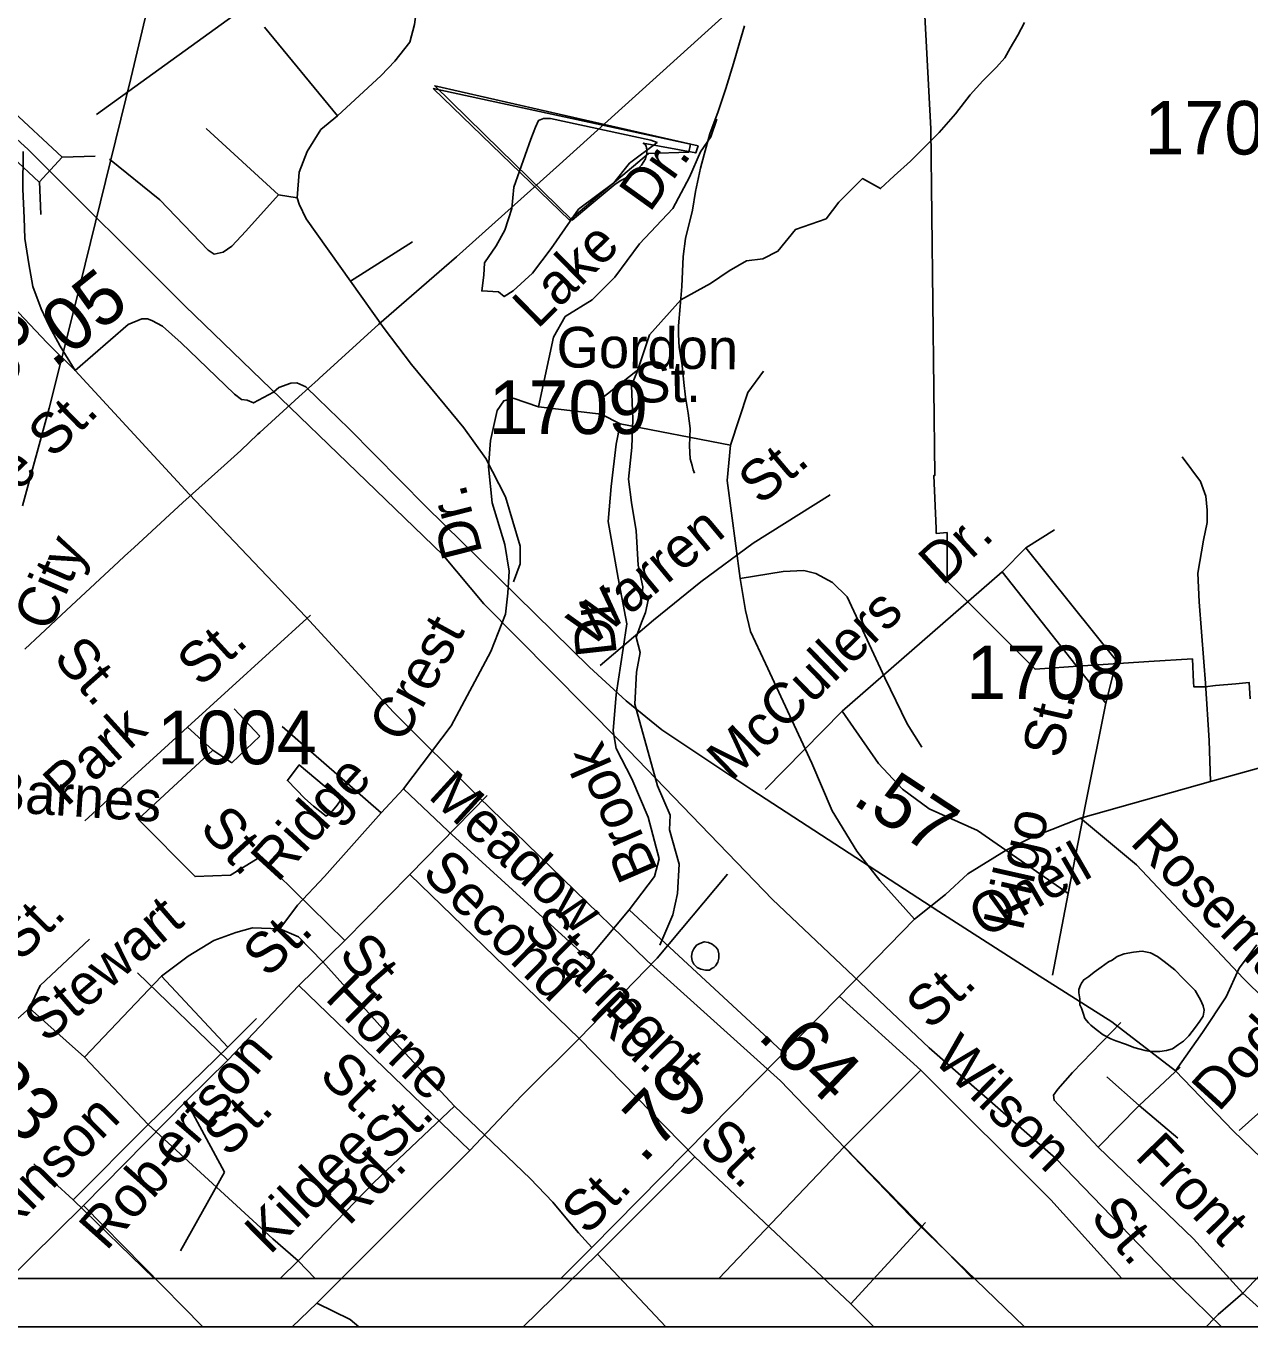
# Model space of a CAD drawing. Extents: x 2169602 to 2449496, y 721995 to 810662.
# Drawn here: x 2400191 to 2403047, y 758895 to 761931 of the extents above; entities that cross this region are included whole.
import ezdxf

# ---------------------------------------------------------------- set-up
doc = ezdxf.new("R2010")
doc.units = 0
doc.layers.add('Default', color=7, linetype='Continuous')

msp = doc.modelspace()

# ---------------------------------------------------------------- linework, layer by layer
at = {"layer": 'Default'}
for p, q in [((2400355.4, 761724.6), (2402242.2, 763086.8)), ((2400918.3, 761721.5), (2400747.8, 761928.8)), ((2400780.1, 761537.2), (2400611.9, 761691.6)), ((2400275.4, 761624.8), (2400352.5, 761627.7)), ((2400222.9, 761568.2), (2400225.9, 761491.1)), ((2400823.8, 761530.3), (2400780.1, 761537.2)), ((2400948.2, 761335.7), (2401093.3, 761427.8)), ((2401834.9, 760953), (2401577.1, 761002.9)), ((2402523.8, 760713.7), (2402590.6, 760755.2)), ((2402468.5, 760657.3), (2402523.8, 760713.7)), ((2402735.7, 760450), (2402523.8, 760713.7)), ((2402095.4, 760332.5), (2402468.5, 760657.3)), ((2402710.4, 760350.9), (2402468.5, 760657.3)), ((2400855.2, 760556.4), (2400568, 760294.8)), ((2402710.4, 760350.9), (2402735.7, 760450)), ((2400737.1, 760274), (2400676.5, 760337.8)), ((2401915.7, 760149.4), (2402095.4, 760332.5)), ((2400568, 760294.8), (2400328.7, 760076.2)), ((2400671.7, 760211.8), (2400737.1, 760274)), ((2401019.5, 760094.8), (2400788.6, 760296.6)), ((2400627, 760241.3), (2400671.7, 760211.8)), ((2401086.5, 759951), (2401266.8, 760135.2)), ((2400934.9, 759797), (2400737.1, 759991.6)), ((2400934.9, 759797), (2401086.5, 759951)), ((2401086.5, 759951), (2401482.2, 759568.1)), ((2401664, 759755.5), (2401828.3, 759951.8)), ((2402586, 759716.3), (2402622.9, 759906.4)), ((2401598.7, 759868.5), (2401502.7, 759754.4)), ((2401965.4, 759528.6), (2401598.7, 759868.5)), ((2400828, 759691.7), (2400934.9, 759797)), ((2401482.2, 759568.1), (2401664, 759755.5)), ((2400507.7, 759714), (2400328, 759525.1)), ((2400662.1, 759517.8), (2400451.5, 759721.2)), ((2400662.1, 759517.8), (2400828, 759691.7)), ((2400828, 759691.7), (2401226.9, 759307.2)), ((2402279.3, 759494.4), (2402088.6, 759667.3)), ((2400005.5, 759466.4), (2400199, 759639.1)), ((2400199, 759639.1), (2400328, 759525.1)), ((2400662, 759548.1), (2400728.8, 759614.9)), ((2401482.2, 759568.1), (2401751.6, 759291.9)), ((2400328, 759525.1), (2400476.4, 759367.8)), ((2400564.8, 759422.1), (2400662.1, 759517.8)), ((2403021.4, 759353.5), (2403214.9, 759526.3)), ((2402279.3, 759494.4), (2402099.9, 759315.6)), ((2402788.4, 759412.3), (2402884.2, 759501.3)), ((2402788.4, 759412.3), (2402713.1, 759479.1)), ((2400325.5, 759178.8), (2400564.8, 759422.1)), ((2400564.8, 759422.1), (2400654.2, 759256.2)), ((2402692.6, 759314.8), (2402788.4, 759412.3)), ((2402788.4, 759412.3), (2402879, 759335.4)), ((2400476.4, 759367.8), (2400301.1, 759191.6)), ((2402099.9, 759315.6), (2402400.6, 759007.9)), ((2400301.1, 759191.6), (2400209.6, 759275.4)), ((2401524.4, 759064.7), (2401751.6, 759291.9)), ((2401751.6, 759291.9), (2402115.8, 758949.2)), ((2400654.2, 759256.2), (2400552, 759072.7)), ((2400490.6, 759007.9), (2400301.1, 759191.6)), ((2400325.5, 759178.8), (2400604, 758895)), ((2402115.8, 758949.2), (2402290.1, 759139.1)), ((2401351.4, 758895), (2401524.4, 759064.7)), ((2400784.4, 759007.9), (2400826.2, 759049.7)), ((2400826.2, 759049.7), (2400865.5, 759007.9)), ((2394416.8, 759007.9), (2405610.9, 759007.9)), ((2394416.8, 759007.9), (2405610.9, 759007.9)), ((2403117.2, 758895), (2403030.2, 758974.2)), ((2400812, 758895), (2400869.5, 758950.7)), ((2397432.6, 758895), (2408626.7, 758895)), ((2397432.6, 758895), (2408626.7, 758895))]:
    msp.add_line(p, q, dxfattribs=at)
for points in [[(2400851, 766726.3), (2400842.5, 766575.8), (2400839.9, 766339.8), (2400835.6, 765996), (2400818.1, 765338.4), (2400840.8, 764831.1), (2400846.7, 763934.8), (2400833.1, 763794.7), (2400836.5, 763647.5), (2400818.5, 763466.1), (2400781.8, 763328.7), (2400733.9, 763084.7), (2400632.1, 762628), (2400510.6, 762123.4), (2400435.4, 761808.7), (2400306.2, 761280.1), (2400245.5, 761039), (2400183.1, 760811.5)], [(2396129.6, 763877.6), (2396680.6, 763791.4), (2397139, 763715.8), (2397435.1, 763663.6), (2397561.3, 763644.4), (2397693.5, 763605.1), (2397827.5, 763567.8), (2397896.5, 763550), (2397996.9, 763511.8), (2398101.8, 763473.6), (2398170.6, 763445.2), (2398269.9, 763394.4), (2398470.8, 763267.7), (2398593.3, 763184.4), (2398657.6, 763126.8), (2398901, 762898.2), (2399194.5, 762599.9), (2399845.9, 761961.9), (2400196.3, 761642.8)], [(2403048.5, 762768.7), (2402893.2, 762923.4), (2402644, 762698.7), (2402380.5, 762464.9), (2402119, 762227.3), (2401887.5, 762017.2), (2401435.7, 761608.3), (2401195.5, 761392.1), (2401166.7, 761367.8), (2401014.7, 761235.7), (2400875.2, 761108.9), (2400872.5, 761106.4), (2400827.7, 761065.7), (2400736.5, 760982.7), (2400732.2, 760978.7), (2400692.5, 760940.5), (2400653.2, 760905.2), (2400594.2, 760852.5), (2400557.2, 760818.9), (2400443.2, 760714.1), (2400421.2, 760693.8), (2400406.7, 760680.4), (2400297.5, 760578.8), (2400261.7, 760545.6)], [(2403048.5, 762768.7), (2402893.2, 762923.4), (2402644, 762698.7), (2402380.5, 762464.9), (2402119, 762227.3), (2401887.5, 762017.2), (2401435.7, 761608.3), (2401195.5, 761392.1), (2401166.7, 761367.8), (2401014.7, 761235.7), (2400875.2, 761108.9), (2400872.5, 761106.4), (2400827.7, 761065.7), (2400736.5, 760982.7), (2400732.2, 760978.7), (2400692.5, 760940.5), (2400653.2, 760905.2), (2400594.2, 760852.5), (2400557.2, 760818.9), (2400443.2, 760714.1), (2400421.2, 760693.8), (2400406.7, 760680.4), (2400297.5, 760578.8), (2400261.7, 760545.6)], [(2403047.4, 760360.8), (2403045.4, 760398.8), (2403013.9, 760396.1), (2402966.2, 760391.7), (2402942.4, 760389), (2402915.9, 760389.2), (2402914.9, 760399.7), (2402912.7, 760454), (2402810.7, 760448.4), (2402657.2, 760438.3), (2402545.4, 760430.1), (2402340.7, 760635.7), (2402340.4, 760748.9), (2402314.9, 760747.2), (2402314.7, 760758.7), (2402309.4, 760882.2), (2402311.4, 760881.8), (2402302.4, 761691.1), (2402269.7, 762307.4)], [(2403047.4, 760360.8), (2403045.4, 760398.8), (2403013.9, 760396.1), (2402966.2, 760391.7), (2402942.4, 760389), (2402915.9, 760389.2), (2402914.9, 760399.7), (2402912.7, 760454), (2402810.7, 760448.4), (2402657.2, 760438.3), (2402545.4, 760430.1), (2402340.7, 760635.7), (2402340.4, 760748.9), (2402314.9, 760747.2), (2402314.7, 760758.7), (2402309.4, 760882.2), (2402311.4, 760881.8), (2402302.4, 761691.1), (2402269.7, 762307.4)], [(2400918.3, 761721.5), (2401019.6, 761816), (2401051.9, 761849.4), (2401086.4, 761893.1), (2401098, 761934.6), (2401104.9, 761987.6), (2401111.8, 762095.8), (2401107.2, 762170.7)], [(2401670.2, 759786.2), (2401700.2, 759856.9), (2401711, 759906.8), (2401715.1, 759975), (2401692.7, 760055.6), (2401694.3, 760089.7), (2401664.4, 760157.9), (2401612, 760348.4), (2401615.3, 760423.2), (2401624.5, 760469), (2401615.1, 760504.7), (2401627.2, 760538.9), (2401636.6, 760562.7), (2401643.2, 760590.9), (2401628.2, 760596.7), (2401630.5, 760622.7), (2401619.5, 760672.7), (2401614.5, 760753.4), (2401603.7, 760819.1), (2401597, 760874), (2401604.5, 760947.2), (2401607, 761013.7), (2401604.2, 761092.1), (2401618, 761126.2), (2401646.1, 761210.8), (2401719.3, 761292.3), (2401788.3, 761330.6), (2401831.6, 761359.7), (2401872.3, 761383), (2401910.6, 761387.9), (2401945.5, 761405.4), (2401986.3, 761456.1), (2402057.8, 761481.1), (2402087.7, 761520.2), (2402142.6, 761575.1), (2402185.1, 761551.8), (2402216.9, 761581.8), (2402255.1, 761615.8), (2402322.1, 761682.3), (2402360.1, 761726.5), (2402393.9, 761770.9), (2402423.4, 761802.9), (2402455.6, 761835), (2402475.3, 761857.1), (2402487.2, 761879.3), (2402505.4, 761909.4), (2402521, 761939.5)], [(2401751.2, 760887.3), (2401747.5, 760895.2), (2401745.2, 760905.2), (2401741.1, 760921.3), (2401738.9, 760951.2), (2401740.9, 760991.5), (2401736.2, 761027.5), (2401730.3, 761065.3), (2401726.2, 761099.2), (2401722.3, 761139.1), (2401715.5, 761181.1), (2401713.2, 761211), (2401713.2, 761231.3), (2401717.6, 761276.9), (2401721, 761323), (2401724.5, 761393.1), (2401730.3, 761435.2), (2401746.1, 761501.4), (2401753.2, 761545.3), (2401765.3, 761599.4), (2401773.1, 761631.5), (2401786.7, 761679.3), (2401806.3, 761731.5), (2401824.4, 761785.6), (2401842, 761843.7), (2401855.6, 761891.6), (2401867.4, 761931.6)], [(2401362.7, 761578.4), (2401465.4, 761478.4), (2401509.7, 761515.3), (2401565.7, 761561.8), (2401578.9, 761570.5), (2401601.4, 761581.9), (2401602.4, 761582.4), (2401626.9, 761606.4), (2401636.4, 761620.8), (2401639.7, 761633.9), (2401639.9, 761642.1), (2401637.9, 761651.1), (2401635.9, 761654.5), (2401631.4, 761657.4), (2401753.9, 761635), (2401759.2, 761651.5), (2401144.7, 761791.4), (2401296.7, 761642.6), (2401362.7, 761578.4)], [(2401362.7, 761578.4), (2401465.4, 761478.4), (2401509.7, 761515.3), (2401565.7, 761561.8), (2401578.9, 761570.5), (2401601.4, 761581.9), (2401602.4, 761582.4), (2401626.9, 761606.4), (2401636.4, 761620.8), (2401639.7, 761633.9), (2401639.9, 761642.1), (2401637.9, 761651.1), (2401635.9, 761654.5), (2401631.4, 761657.4), (2401753.9, 761635), (2401759.2, 761651.5), (2401144.7, 761791.4), (2401296.7, 761642.6), (2401362.7, 761578.4)], [(2400823.8, 761530.3), (2400828.4, 761590.2), (2400846.9, 761638.6), (2400879.1, 761689.3), (2400918.3, 761721.5)], [(2401386.6, 761042.8), (2401421.6, 761205), (2401449, 761253.2), (2401512.2, 761292.3), (2401565.4, 761344.7), (2401622.8, 761422.9), (2401700.2, 761505.2), (2401739.3, 761578.4), (2401765, 761637.4), (2401789.2, 761672.4), (2401803.3, 761714)], [(2400305.9, 761127.1), (2400240.3, 761191.4), (2400106.6, 761332.7), (2399930, 761516.8), (2399861.9, 761591.3), (2399786.3, 761687.1)], [(2400184.8, 761638.6), (2400183.6, 761550.3), (2400187.2, 761483.8), (2400188.2, 761435.2), (2400197.4, 761376.2), (2400207.5, 761323.2), (2400226.4, 761270.9), (2400245.4, 761231.2), (2400271.2, 761183.9), (2400305.9, 761127.1)], [(2400196.3, 761642.8), (2400562.8, 761277.1), (2401163.8, 760696.7), (2401259.1, 760582.5), (2401576.9, 760262.2), (2401932.9, 759892.4), (2402298.5, 759546.6), (2402594, 759288.4), (2402853.3, 759020), (2402980.7, 758895)], [(2400780.1, 761537.2), (2400704.1, 761452), (2400671.8, 761417.5), (2400651.1, 761403.6), (2400630.3, 761399), (2400616.5, 761408.3), (2400503.7, 761525.7), (2400386.2, 761620.2)], [(2400948.2, 761335.7), (2400844.6, 761480.8), (2400828.4, 761515.4), (2400823.8, 761530.3)], [(2401328.3, 760634.3), (2401344.4, 760675.7), (2401344.4, 760717.2), (2401309.9, 760832.4), (2401263.8, 760922.2), (2401213.1, 760993.6), (2401091, 761141), (2401026.5, 761225.1), (2400948.2, 761335.7)], [(2400768.8, 761076.7), (2400721.9, 761051.4), (2400707, 761057.8), (2400694, 761059.6), (2400677.6, 761071.6), (2400592.8, 761153.6), (2400553.1, 761192.1), (2400509.6, 761230.5), (2400485, 761243.8), (2400474.7, 761247.5), (2400461.7, 761247.6), (2400429.5, 761234.3), (2400305.9, 761127.1)], [(2400305.9, 761127.1), (2400572, 760838.3), (2400844.4, 760552), (2401048.8, 760330), (2401246.8, 760132), (2401640.3, 759749.8), (2401951.2, 759469.2), (2402272.2, 759135.6), (2402520.8, 758895)], [(2401625, 761133.1), (2401536.7, 761063.9)], [(2401834.9, 760953), (2401875.6, 761076.1), (2401912.2, 761126)], [(2402873.2, 759492.6), (2402724.3, 759607.3), (2402555.3, 759714.5), (2402320.7, 759864.6), (2401884.3, 760148.4), (2401675, 760288.4), (2401591.7, 760356.5), (2401506, 760434.7), (2401123.8, 760809.9), (2400944.1, 760992.2), (2400872.2, 761061.5), (2400843.8, 761089.3), (2400823, 761098.1), (2400809.1, 761097.5), (2400781.3, 761087.6), (2400768.8, 761076.7)], [(2401386.6, 761042.8), (2401328.2, 761062.9), (2401306, 761056.1), (2401290.6, 761033.8), (2401275.2, 760963.7), (2401270.1, 760902.1), (2401278.6, 760818.3), (2401308.6, 760720.8), (2401318.8, 760659.2), (2401315.4, 760607.9), (2401310.3, 760558.3), (2401276.1, 760471.1), (2401182.9, 760298.3), (2401071.7, 760151.2)], [(2401577.1, 761002.9), (2401533.5, 761025.3), (2401386.6, 761042.8)], [(2401598.7, 759868.5), (2401657.8, 759946.7), (2401668.6, 759987.5), (2401642.8, 760084.8), (2401604.5, 760174.6), (2401567.9, 760245.3), (2401561.3, 760286), (2401567.9, 760370.8), (2401584.6, 760478.1), (2401592.9, 760536.3), (2401572.9, 760642.8), (2401549.6, 760775), (2401556.3, 760856.5), (2401567.9, 760955.5), (2401577.1, 761002.9)], [(2401857.4, 760642), (2401827.4, 760870.7), (2401834.9, 760953)], [(2402954.9, 760168.3), (2402951.5, 760264.1), (2402942.9, 760397.5), (2402939.5, 760447.1), (2402928.4, 760587.4), (2402925, 760654.1), (2402938.7, 760731.1), (2402947.2, 760772.1), (2402947.2, 760801.2), (2402943.8, 760833.7), (2402931.8, 760867.9), (2402889.1, 760926.1)], [(2401531, 760438.5), (2401655.4, 760544.4), (2401766, 760634.3), (2401888.1, 760724.1), (2402067.7, 760837)], [(2401857.4, 760642), (2401958, 760657.8), (2402006.2, 760660.3), (2402033.7, 760653.6), (2402072.7, 760632.8), (2402106.8, 760598.7), (2402195, 760409.9), (2402247.4, 760302.6), (2402281.5, 760247.8)], [(2402264, 759846.9), (2402183.4, 759936.7), (2402129.3, 760005.7), (2402071.9, 760099.7), (2402024.5, 760211.2), (2401916.4, 760443.2), (2401881.5, 760518), (2401869.8, 760567.1), (2401857.4, 760642)], [(2400261.7, 760545.6), (2400247.2, 760532.1), (2400225, 760511.2), (2400188.7, 760477.2)], [(2400261.7, 760545.6), (2400247.2, 760532.1), (2400225, 760511.2), (2400188.7, 760477.2)], [(2402095.4, 760332.5), (2402180.6, 760210.4), (2402235.9, 760150.5), (2402298.1, 760104.5), (2402410.9, 760053.8), (2402622.9, 759906.4)], [(2402622.9, 759906.4), (2402664.3, 760118.3), (2402710.4, 760350.9)], [(2400737.1, 759991.6), (2400668.5, 759949.4), (2400585.5, 759946.2), (2400453.1, 760080.2), (2400627, 760241.3), (2400568, 760294.8)], [(2403170.4, 760228.2), (2402954.9, 760168.3), (2402651.3, 760082.4), (2402585, 760055.9), (2402540.3, 760038.7), (2402478.3, 760007.7), (2402388.9, 759952.7), (2402336.3, 759904.7), (2402264, 759846.9), (2402086.1, 759663.9), (2401947.2, 759522.6), (2401511.3, 759080.4), (2401438.7, 759007.9)], [(2400891.9, 760086.8), (2400905.8, 760098.9), (2400913.8, 760109), (2400917.5, 760112.9), (2400925.9, 760125), (2400828.9, 760206.6), (2400801.3, 760170.2), (2400841.4, 760128.4), (2400861.9, 760110.7), (2400891.9, 760086.8)], [(2401071.7, 760151.2), (2401019.5, 760094.8)], [(2401502.7, 759754.4), (2401176, 760052), (2401071.7, 760151.2)], [(2401019.5, 760094.8), (2400887.8, 759946), (2400824.5, 759879.2), (2400783.5, 759824.5)], [(2402651.3, 760082.4), (2402782.2, 759973.3), (2403031.9, 759708.2), (2403328.7, 759415.7), (2403366.3, 759381.5), (2403388.5, 759355.8), (2403393.7, 759338.7), (2403385.1, 759314.8), (2403339.8, 759261.8)], [(2400507.7, 759714), (2400569.9, 759760.1), (2400629.8, 759796.9), (2400680.5, 759815.3), (2400719.6, 759826.9), (2400783.5, 759824.5)], [(2400783.5, 759824.5), (2400827.1, 759805.7), (2400883.5, 759747.5), (2401044.3, 759567.9), (2401190.6, 759410.6)], [(2400199, 759639.1), (2400224.4, 759692.1), (2400339.6, 759800.4)], [(2401800, 759738.2), (2401805.5, 759746.2), (2401807.6, 759756.1), (2401807.6, 759766.2), (2401805.5, 759776.3), (2401799.6, 759782), (2401791.8, 759788.1), (2401783.4, 759792.1), (2401773.5, 759794), (2401763.5, 759789.9), (2401755.7, 759785.8), (2401749.5, 759777.8), (2401745.6, 759769.9), (2401743.6, 759759.6), (2401745.8, 759749.6), (2401749.5, 759741.7), (2401757.5, 759734), (2401765.9, 759729.9), (2401776.2, 759728), (2401786, 759728.1), (2401791.8, 759732.1), (2401795.9, 759733.9), (2401800, 759738.2)], [(2403062.9, 759786.9), (2403022, 759732.2), (2402991.7, 759665.3), (2402936.2, 759582.1), (2402873.2, 759492.6)], [(2402756.2, 759555.4), (2402766.3, 759551.5), (2402776.3, 759547.5), (2402790.5, 759543.7), (2402802.2, 759539.9), (2402814.7, 759537.7), (2402826.6, 759537.9), (2402836.4, 759538), (2402852.4, 759540.1), (2402866.1, 759544.1), (2402880.3, 759554.1), (2402892.2, 759562.4), (2402904.1, 759574.4), (2402919.6, 759594.4), (2402930.1, 759608.6), (2402937.9, 759620.4), (2402939.9, 759634.7), (2402937.7, 759644.4), (2402931.5, 759658.7), (2402919.4, 759680.4), (2402907.5, 759692.3), (2402891.3, 759708.2), (2402871.5, 759728.2), (2402847.1, 759748.1), (2402831.3, 759759.9), (2402815.1, 759768), (2402795.4, 759771.8), (2402775.1, 759769.6), (2402753.1, 759765.6), (2402737.1, 759759.5), (2402725.3, 759751.1), (2402716.8, 759747.1), (2402699.6, 759735.1), (2402683.4, 759723), (2402671.1, 759713), (2402659.2, 759705.2), (2402653.7, 759697.1), (2402651.6, 759692.9), (2402647.5, 759683), (2402647.3, 759674.9), (2402649.8, 759660.8), (2402650, 759646.9), (2402653.7, 759639), (2402657.8, 759627.1), (2402661.7, 759615.1), (2402670.3, 759604.9), (2402676, 759599.2), (2402687.9, 759589.2), (2402704.3, 759577), (2402722.2, 759567.5), (2402734.3, 759563.2), (2402756.2, 759555.4)], [(2400507.7, 759714), (2400662, 759548.1)], [(2402692.6, 759314.8), (2402590, 759424.3), (2402588.3, 759436.3), (2402598.5, 759450), (2402632.7, 759489.3), (2402745.6, 759605.6)], [(2400662, 759548.1), (2400547.6, 759436.7), (2400476.4, 759367.8)], [(2401226.9, 759307.2), (2401348.1, 759434.9), (2401482.2, 759568.1)], [(2402279.3, 759494.4), (2402582, 759191.6), (2402747.6, 759007.9)], [(2402873.2, 759492.6), (2403008.1, 759352.6), (2403206.8, 759160.8), (2403030.2, 758974.2), (2402972.5, 758923.9), (2402965.3, 758916.6)], [(2400826.2, 759049.7), (2401003, 759232.6), (2401190.6, 759410.6)], [(2401190.6, 759410.6), (2401367.6, 759241.2), (2401420.6, 759186.5), (2401454.8, 759145.4), (2401480.5, 759114.7), (2401511.3, 759080.4)], [(2400476.4, 759367.8), (2400767.2, 759101), (2400826.2, 759049.7)], [(2400869.5, 758950.7), (2401086.5, 759167.6), (2401226.9, 759307.2)], [(2401807.7, 759007.9), (2402099.9, 759315.6)], [(2403030.2, 758974.2), (2402915, 759101), (2402692.6, 759314.8)], [(2400045.2, 758895), (2400140.4, 758996.1), (2400325.5, 759178.8)], [(2401683.7, 758895), (2401524.4, 759064.7)], [(2400869.5, 758950.7), (2400947.7, 758912.4), (2400967.5, 758895)], [(2402115.8, 758949.2), (2402169.4, 758895)], [(2402965.3, 758916.6), (2402944.4, 758895)]]:
    msp.add_lwpolyline(points, dxfattribs=at)
for points in [[(2401140.9, 761785.6), (2401459.3, 761477.8), (2401643.8, 761633.5), (2401737.9, 761637.1), (2401741.5, 761655.2)], [(2400151.7, 761739.9), (2400275.6, 761625.1), (2400222, 761567.1), (2400098, 761682)], [(2401414.9, 761715.6), (2401649.4, 761664.9), (2401663.6, 761659.1), (2401599.5, 761610.8), (2401562.9, 761565.1), (2401480.6, 761503.5), (2401416.6, 761412.1), (2401373.3, 761354.7), (2401327.6, 761313.1), (2401306.8, 761299.8), (2401293.5, 761310.6), (2401254.4, 761313.1), (2401259.4, 761349.7), (2401261.1, 761378.8), (2401288.5, 761417.9), (2401308.5, 761454.5), (2401325.1, 761505.2), (2401329.3, 761555.1), (2401369.2, 761667.4), (2401380, 761694.8), (2401386.6, 761710.6), (2401398.3, 761715.6)]]:
    msp.add_lwpolyline(points, close=True, dxfattribs=at)

# ---------------------------------------------------------------- texts
for s, p in [('1709', (2402801.1, 761631.3)), ('1709', (2401270.7, 760979)), ('1708', (2402385.2, 760360.2)), ('1004', (2400497.4, 760208.4))]:
    msp.add_text(s, height=125, dxfattribs=at).set_placement(p)
for s, height, rotation, p in [('Dr.', 95, 54.2655, (2401646.4, 761493.8)), ('Lake', 95, 44.4977, (2401384.4, 761222.1)), ('.05', 125, 38.6942, (2400256, 761130.5)), ('.60', 125, 76.6763, (2400151.9, 761030.1)), ('Gordon', 95, 359.3349, (2401428.6, 761134.6)), ('St.', 95, 0.7081, (2401611.1, 761052.2)), ('St.', 95, 44.3186, (2400253.6, 760919.6)), ('Iron- dale', 95, 43.4652, (2399833.2, 760522.2)), ('St.', 95, 40.2566, (2401904.8, 760810.6)), ('Dr.', 95, 104.2023, (2401256.8, 760701.7)), ('Warren', 95, 39.7193, (2401507.2, 760478.3)), ('Dr.', 95, 42.7362, (2402329.4, 760622.7)), ('City', 95, 66.5411, (2400246.3, 760513.9)), ('Dr.', 95, 96.2733, (2401570.1, 760464.7)), ('McCullers', 95, 44.077, (2401837, 760166)), ('Crest', 95, 61.2776, (2401070.3, 760253.8)), ('St.', 95, 42.204, (2400598.2, 760386)), ('St.', 95, 311.4582, (2400251.9, 760454.3)), ('St.', 95, 77.2883, (2402607, 760219.2)), ('Park', 95, 42.2041, (2400285.7, 760106.9)), ('Brook', 95, 113.429, (2401667.1, 759960.5)), ('Ridge', 95, 47.5784, (2400778.2, 759930)), ('Barnes', 95, 356.2984, (2400102.7, 760099.5)), ('Meadow', 95, 317.5821, (2401126.6, 760131.4)), ('.57', 125, 326.6329, (2402115.5, 760118.5)), ('St.', 95, 312.4845, (2400593.2, 760057.4)), ('Kilgo', 95, 77.2883, (2402516.2, 759816.3)), ('Rosemary', 95, 314.6667, (2402764.5, 760023.7)), ('Oneil', 95, 29.9365, (2402427.3, 759800.7)), ('Second', 95, 315.3341, (2401111.6, 759951)), ('St.', 95, 45.3286, (2400178.9, 759745)), ('Stewart', 95, 40.7449, (2400238.4, 759555.5)), ('St.', 95, 45.3174, (2400756, 759707.3)), ('Starmont', 95, 315.2892, (2401347, 759820.7)), ('St.', 95, 311.0236, (2400917.6, 759763.2)), ('St.', 95, 44.0697, (2402301.2, 759585.6)), ('Horne', 95, 315.3223, (2400886.2, 759660.5)), ('Rd.', 95, 315.2892, (2401502.7, 759620.1)), ('Dodd', 95, 47.6388, (2402973.8, 759394.7)), ('.64', 125, 316.2328, (2401895, 759571.4)), ('Wilson', 95, 315.3388, (2402304.4, 759518.3)), ('ertson', 95, 49.3251, (2400542.4, 759263.9)), ('.23', 125, 315.0271, (2400030.7, 759481.9)), ('St.', 95, 315.1611, (2400871.5, 759480)), ('.79', 125, 45.6201, (2401631, 759274)), ('St.', 95, 45.8931, (2400664.4, 759288.2)), ('Atkinson', 95, 45.3245, (2400073.1, 759032.6)), ('St.', 95, 44.8464, (2401037.5, 759278.7)), ('Kildee', 95, 44.8464, (2400760, 759061.7)), ('St.', 95, 314.3009, (2401756.6, 759324.4)), ('Front', 95, 314.291, (2402775.7, 759291.1)), ('Rob-', 95, 48.2475, (2400378.4, 759070.4)), ('Rd.', 95, 44.8882, (2400944.2, 759128.8)), ('St.', 95, 46.3402, (2401500.9, 759106.6)), ('St.', 95, 310.9017, (2402671.1, 759150.1))]:
    msp.add_text(s, height=height, rotation=rotation, dxfattribs=at).set_placement(p)

doc.saveas('drawing.dxf')
